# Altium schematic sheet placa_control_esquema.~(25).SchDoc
size A4
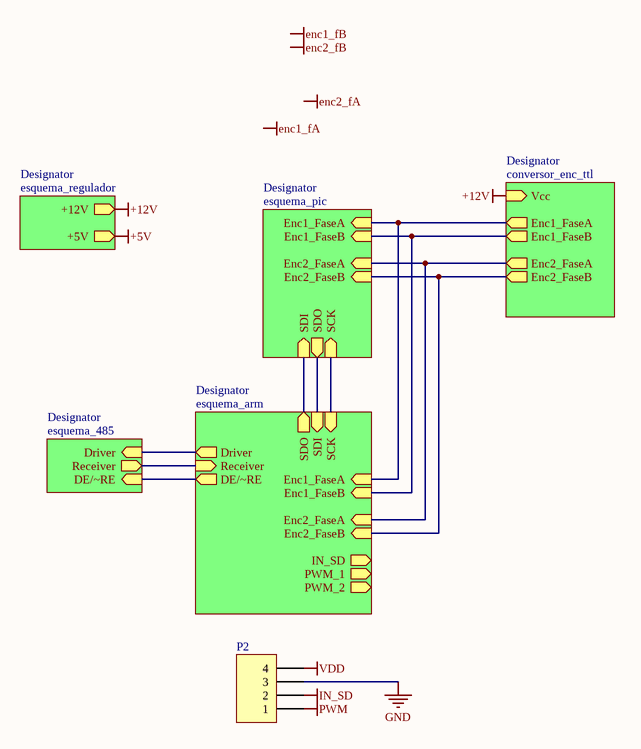
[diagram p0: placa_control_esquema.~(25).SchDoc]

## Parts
P2  Header 4  [HDR1X5]  (value not drawn)

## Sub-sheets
Designator = esquema_regulador: +12V (out), +5V (out)
Designator = esquema_pic: SDI (in), SDO (out), SCK (in), Enc1_FaseA (in), Enc1_FaseB (in), Enc2_FaseA (in), Enc2_FaseB (in)
Designator = esquema_485: Driver (in), Receiver (out), DE/~RE (in)
Designator = esquema_arm: SDI (in), SDO (out), SCK (in), Enc1_FaseA (in), Enc1_FaseB (in), Enc2_FaseA (in), Enc2_FaseB (in), DE/~RE (out), Receiver (in), Driver (out), PWM_1 (out), IN_SD (out), PWM_2 (out)
Designator = conversor_enc_ttl: Enc1_FaseA (out), Enc1_FaseB (out), Enc2_FaseA (out), Enc2_FaseB (out), Vcc (in)

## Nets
+12V: sheet Designator/+12V, sheet Designator/Vcc
GND: P2.3
IN_SD: P2.2
PWM: P2.1
VDD: P2.4
(unnamed): sheet Designator/SDI, sheet Designator/SDO
(unnamed): sheet Designator/SDO, sheet Designator/SDI  [a separate net that carries the same name]
(unnamed): sheet Designator/SCK, sheet Designator/SCK  [a separate net that carries the same name]
(unnamed): sheet Designator/Enc1_FaseA, sheet Designator/Enc1_FaseA, sheet Designator/Enc1_FaseA  [a separate net that carries the same name]
(unnamed): sheet Designator/Enc1_FaseB, sheet Designator/Enc1_FaseB, sheet Designator/Enc1_FaseB  [a separate net that carries the same name]
(unnamed): sheet Designator/Enc2_FaseA, sheet Designator/Enc2_FaseA, sheet Designator/Enc2_FaseA  [a separate net that carries the same name]
(unnamed): sheet Designator/Enc2_FaseB, sheet Designator/Enc2_FaseB, sheet Designator/Enc2_FaseB  [a separate net that carries the same name]
(unnamed): sheet Designator/Driver, sheet Designator/Driver  [a separate net that carries the same name]
(unnamed): sheet Designator/Receiver, sheet Designator/Receiver  [a separate net that carries the same name]
(unnamed): sheet Designator/DE/~RE, sheet Designator/DE/~RE  [a separate net that carries the same name]

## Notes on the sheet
- Labels drawn without touching a wire or pin: enc1_fA, enc1_fB, enc2_fA, enc2_fB

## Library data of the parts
P2 = Header 4: Header, 4-Pin; value: hdr1x5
